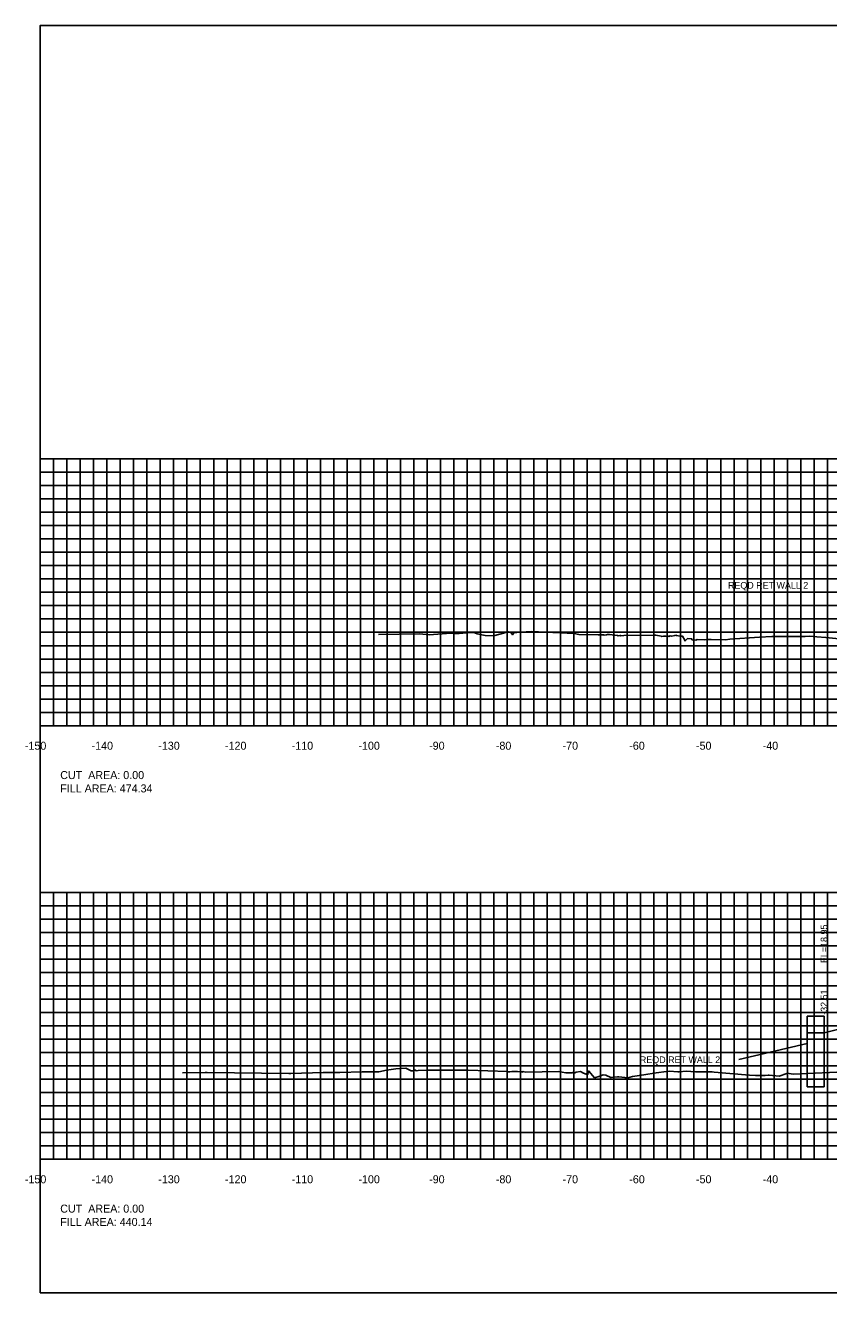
# Model space of a CAD drawing. Extents: x 1797518 to 1804843, y 248068 to 251132.
# Drawn here: x 1802478.8 to 1802599.2, y 250079.4 to 250269.4 of the extents above; entities that cross this region are included whole.
import ezdxf

# ---------------------------------------------------------------- set-up
doc = ezdxf.new("R2010")
doc.units = 0
for name, color, linetype in [('10', 7, 'Continuous'), ('3', 7, 'Continuous'), ('60', 7, 'Continuous'), ('ANNO-TXT', 7, 'Continuous'), ('CL-CNST', 7, 'Continuous'), ('Level 62', 7, 'Continuous'), ('M-ROADS', 7, 'Continuous')]:
    doc.layers.add(name, color=color, linetype=linetype)

msp = doc.modelspace()

# ---------------------------------------------------------------- linework, layer by layer
msp.add_line((1802598.49, 250118.38), (1802598.49, 250120.38))
msp.add_lwpolyline([(1802481, 250079.43), (1802781, 250079.43), (1802781, 250269.43), (1802481, 250269.43)], close=True)
at = {"layer": '3'}
msp.add_line((1802585.74, 250114.4), (1802595.99, 250116.8), dxfattribs=at)
at = {"layer": '60'}
for p, q in [((1802480.94, 250204.43), (1802481, 250204.43)), ((1802481, 250164.43), (1802481, 250204.43)), ((1802480.94, 250194.43), (1802481, 250194.43)), ((1802480.94, 250184.43), (1802481, 250184.43)), ((1802480.94, 250174.43), (1802481, 250174.43)), ((1802480.94, 250164.43), (1802481, 250164.43)), ((1802481, 250164.43), (1802781, 250164.43)), ((1802481, 250164.37), (1802481, 250164.43)), ((1802491, 250164.37), (1802491, 250164.43)), ((1802501, 250164.37), (1802501, 250164.43)), ((1802511, 250164.37), (1802511, 250164.43)), ((1802521, 250164.37), (1802521, 250164.43)), ((1802531, 250164.37), (1802531, 250164.43)), ((1802541, 250164.37), (1802541, 250164.43)), ((1802551, 250164.37), (1802551, 250164.43)), ((1802561, 250164.37), (1802561, 250164.43)), ((1802571, 250164.37), (1802571, 250164.43)), ((1802581, 250164.37), (1802581, 250164.43)), ((1802591, 250164.37), (1802591, 250164.43)), ((1802480.94, 250139.43), (1802481, 250139.43)), ((1802481, 250099.43), (1802481, 250139.43)), ((1802480.94, 250129.43), (1802481, 250129.43)), ((1802480.94, 250119.43), (1802481, 250119.43)), ((1802480.94, 250109.43), (1802481, 250109.43)), ((1802480.94, 250099.43), (1802481, 250099.43)), ((1802481, 250099.43), (1802781, 250099.43)), ((1802481, 250099.37), (1802481, 250099.43)), ((1802491, 250099.37), (1802491, 250099.43)), ((1802501, 250099.37), (1802501, 250099.43)), ((1802511, 250099.37), (1802511, 250099.43)), ((1802521, 250099.37), (1802521, 250099.43)), ((1802531, 250099.37), (1802531, 250099.43)), ((1802541, 250099.37), (1802541, 250099.43)), ((1802551, 250099.37), (1802551, 250099.43)), ((1802561, 250099.37), (1802561, 250099.43)), ((1802571, 250099.37), (1802571, 250099.43)), ((1802581, 250099.37), (1802581, 250099.43)), ((1802591, 250099.37), (1802591, 250099.43))]:
    msp.add_line(p, q, dxfattribs=at)
at = {"layer": 'CL-CNST'}
msp.add_lwpolyline([(1802598.49, 250118.38), (1802621, 250124.01), (1802623, 250124.09), (1802631, 250124.41), (1802655, 250125.28), (1802659, 250125.36), (1802661, 250125.38)], dxfattribs=at)
for points in [[(1802598.49, 250118.38), (1802595.99, 250118.38), (1802595.99, 250120.88), (1802598.49, 250120.88)], [(1802595.99, 250110.29), (1802598.49, 250110.29), (1802598.49, 250118.38), (1802595.99, 250118.38)]]:
    msp.add_lwpolyline(points, close=True, dxfattribs=at)
at = {"layer": 'Level 62'}
for p, q in [((1802481, 250204.43), (1802781, 250204.43)), ((1802481, 250164.43), (1802481, 250204.43)), ((1802483, 250164.43), (1802483, 250204.43)), ((1802485, 250164.43), (1802485, 250204.43)), ((1802487, 250164.43), (1802487, 250204.43)), ((1802489, 250164.43), (1802489, 250204.43)), ((1802491, 250164.43), (1802491, 250204.43)), ((1802493, 250164.43), (1802493, 250204.43)), ((1802495, 250164.43), (1802495, 250204.43)), ((1802497, 250164.43), (1802497, 250204.43)), ((1802499, 250164.43), (1802499, 250204.43)), ((1802501, 250164.43), (1802501, 250204.43)), ((1802503, 250164.43), (1802503, 250204.43)), ((1802505, 250164.43), (1802505, 250204.43)), ((1802507, 250164.43), (1802507, 250204.43)), ((1802509, 250164.43), (1802509, 250204.43)), ((1802511, 250164.43), (1802511, 250204.43)), ((1802513, 250164.43), (1802513, 250204.43)), ((1802515, 250164.43), (1802515, 250204.43)), ((1802517, 250164.43), (1802517, 250204.43)), ((1802519, 250164.43), (1802519, 250204.43)), ((1802521, 250164.43), (1802521, 250204.43)), ((1802523, 250164.43), (1802523, 250204.43)), ((1802525, 250164.43), (1802525, 250204.43)), ((1802527, 250164.43), (1802527, 250204.43)), ((1802529, 250164.43), (1802529, 250204.43)), ((1802531, 250164.43), (1802531, 250204.43)), ((1802533, 250164.43), (1802533, 250204.43)), ((1802535, 250164.43), (1802535, 250204.43)), ((1802537, 250164.43), (1802537, 250204.43)), ((1802539, 250164.43), (1802539, 250204.43)), ((1802541, 250164.43), (1802541, 250204.43)), ((1802543, 250164.43), (1802543, 250204.43)), ((1802545, 250164.43), (1802545, 250204.43)), ((1802547, 250164.43), (1802547, 250204.43)), ((1802549, 250164.43), (1802549, 250204.43)), ((1802551, 250164.43), (1802551, 250204.43)), ((1802553, 250164.43), (1802553, 250204.43)), ((1802555, 250164.43), (1802555, 250204.43)), ((1802557, 250164.43), (1802557, 250204.43)), ((1802559, 250164.43), (1802559, 250204.43)), ((1802561, 250164.43), (1802561, 250204.43)), ((1802563, 250164.43), (1802563, 250204.43)), ((1802565, 250164.43), (1802565, 250204.43)), ((1802567, 250164.43), (1802567, 250204.43)), ((1802569, 250164.43), (1802569, 250204.43)), ((1802571, 250164.43), (1802571, 250204.43)), ((1802573, 250164.43), (1802573, 250204.43)), ((1802575, 250164.43), (1802575, 250204.43)), ((1802577, 250164.43), (1802577, 250204.43)), ((1802579, 250164.43), (1802579, 250204.43)), ((1802581, 250164.43), (1802581, 250204.43)), ((1802583, 250164.43), (1802583, 250204.43)), ((1802585, 250164.43), (1802585, 250204.43)), ((1802587, 250164.43), (1802587, 250204.43)), ((1802589, 250164.43), (1802589, 250204.43)), ((1802591, 250164.43), (1802591, 250204.43)), ((1802593, 250164.43), (1802593, 250204.43)), ((1802595, 250164.43), (1802595, 250204.43)), ((1802597, 250164.43), (1802597, 250204.43)), ((1802599, 250164.43), (1802599, 250204.43)), ((1802481, 250202.43), (1802781, 250202.43)), ((1802481, 250200.43), (1802781, 250200.43)), ((1802481, 250198.43), (1802781, 250198.43)), ((1802481, 250196.43), (1802781, 250196.43)), ((1802481, 250194.43), (1802781, 250194.43)), ((1802481, 250192.43), (1802781, 250192.43)), ((1802481, 250190.43), (1802781, 250190.43)), ((1802481, 250188.43), (1802781, 250188.43)), ((1802481, 250186.43), (1802781, 250186.43)), ((1802481, 250184.43), (1802781, 250184.43)), ((1802481, 250182.43), (1802781, 250182.43)), ((1802481, 250180.43), (1802781, 250180.43)), ((1802481, 250178.43), (1802781, 250178.43)), ((1802481, 250176.43), (1802781, 250176.43)), ((1802481, 250174.43), (1802781, 250174.43)), ((1802481, 250172.43), (1802781, 250172.43)), ((1802481, 250170.43), (1802781, 250170.43)), ((1802481, 250168.43), (1802781, 250168.43)), ((1802481, 250166.43), (1802781, 250166.43)), ((1802481, 250164.43), (1802781, 250164.43)), ((1802481, 250139.43), (1802781, 250139.43)), ((1802481, 250099.43), (1802481, 250139.43)), ((1802483, 250099.43), (1802483, 250139.43)), ((1802485, 250099.43), (1802485, 250139.43)), ((1802487, 250099.43), (1802487, 250139.43)), ((1802489, 250099.43), (1802489, 250139.43)), ((1802491, 250099.43), (1802491, 250139.43)), ((1802493, 250099.43), (1802493, 250139.43)), ((1802495, 250099.43), (1802495, 250139.43)), ((1802497, 250099.43), (1802497, 250139.43)), ((1802499, 250099.43), (1802499, 250139.43)), ((1802501, 250099.43), (1802501, 250139.43)), ((1802503, 250099.43), (1802503, 250139.43)), ((1802505, 250099.43), (1802505, 250139.43)), ((1802507, 250099.43), (1802507, 250139.43)), ((1802509, 250099.43), (1802509, 250139.43)), ((1802511, 250099.43), (1802511, 250139.43)), ((1802513, 250099.43), (1802513, 250139.43)), ((1802515, 250099.43), (1802515, 250139.43)), ((1802517, 250099.43), (1802517, 250139.43)), ((1802519, 250099.43), (1802519, 250139.43)), ((1802521, 250099.43), (1802521, 250139.43)), ((1802523, 250099.43), (1802523, 250139.43)), ((1802525, 250099.43), (1802525, 250139.43)), ((1802527, 250099.43), (1802527, 250139.43)), ((1802529, 250099.43), (1802529, 250139.43)), ((1802531, 250099.43), (1802531, 250139.43)), ((1802533, 250099.43), (1802533, 250139.43)), ((1802535, 250099.43), (1802535, 250139.43)), ((1802537, 250099.43), (1802537, 250139.43)), ((1802539, 250099.43), (1802539, 250139.43)), ((1802541, 250099.43), (1802541, 250139.43)), ((1802543, 250099.43), (1802543, 250139.43)), ((1802545, 250099.43), (1802545, 250139.43)), ((1802547, 250099.43), (1802547, 250139.43)), ((1802549, 250099.43), (1802549, 250139.43)), ((1802551, 250099.43), (1802551, 250139.43)), ((1802553, 250099.43), (1802553, 250139.43)), ((1802555, 250099.43), (1802555, 250139.43)), ((1802557, 250099.43), (1802557, 250139.43)), ((1802559, 250099.43), (1802559, 250139.43)), ((1802561, 250099.43), (1802561, 250139.43)), ((1802563, 250099.43), (1802563, 250139.43)), ((1802565, 250099.43), (1802565, 250139.43)), ((1802567, 250099.43), (1802567, 250139.43)), ((1802569, 250099.43), (1802569, 250139.43)), ((1802571, 250099.43), (1802571, 250139.43)), ((1802573, 250099.43), (1802573, 250139.43)), ((1802575, 250099.43), (1802575, 250139.43)), ((1802577, 250099.43), (1802577, 250139.43)), ((1802579, 250099.43), (1802579, 250139.43)), ((1802581, 250099.43), (1802581, 250139.43)), ((1802583, 250099.43), (1802583, 250139.43)), ((1802585, 250099.43), (1802585, 250139.43)), ((1802587, 250099.43), (1802587, 250139.43)), ((1802589, 250099.43), (1802589, 250139.43)), ((1802591, 250099.43), (1802591, 250139.43)), ((1802593, 250099.43), (1802593, 250139.43)), ((1802595, 250099.43), (1802595, 250139.43)), ((1802597, 250099.43), (1802597, 250139.43)), ((1802599, 250099.43), (1802599, 250139.43)), ((1802481, 250137.43), (1802781, 250137.43)), ((1802481, 250135.43), (1802781, 250135.43)), ((1802481, 250133.43), (1802781, 250133.43)), ((1802481, 250131.43), (1802781, 250131.43)), ((1802481, 250129.43), (1802781, 250129.43)), ((1802481, 250127.43), (1802781, 250127.43)), ((1802481, 250125.43), (1802781, 250125.43)), ((1802481, 250123.43), (1802781, 250123.43)), ((1802481, 250121.43), (1802781, 250121.43)), ((1802481, 250119.43), (1802781, 250119.43)), ((1802481, 250117.43), (1802781, 250117.43)), ((1802481, 250115.43), (1802781, 250115.43)), ((1802481, 250113.43), (1802781, 250113.43)), ((1802481, 250111.43), (1802781, 250111.43)), ((1802481, 250109.43), (1802781, 250109.43)), ((1802481, 250107.43), (1802781, 250107.43)), ((1802481, 250105.43), (1802781, 250105.43)), ((1802481, 250103.43), (1802781, 250103.43)), ((1802481, 250101.43), (1802781, 250101.43)), ((1802481, 250099.43), (1802781, 250099.43))]:
    msp.add_line(p, q, dxfattribs=at)
at = {"layer": 'M-ROADS'}
for points in [[(1802531.72, 250178.09), (1802537.88, 250178.21), (1802539.29, 250178.07), (1802542.54, 250178.3), (1802542.92, 250178.27), (1802543.78, 250178.28), (1802545.38, 250178.38), (1802545.99, 250178.38), (1802546.52, 250178.19), (1802547.68, 250177.97), (1802548.95, 250177.89), (1802550.66, 250178.35), (1802550.79, 250178.43), (1802550.81, 250178.43), (1802550.82, 250178.43), (1802551.17, 250178.52), (1802551.35, 250178.45), (1802551.57, 250178.39), (1802551.72, 250178.16), (1802551.81, 250178.08), (1802552, 250178.35), (1802552.9, 250178.47), (1802553.82, 250178.52), (1802554.62, 250178.54), (1802561.06, 250178.28), (1802561.75, 250178.11), (1802564.65, 250178.08), (1802564.67, 250178.08), (1802565.43, 250178.05), (1802565.52, 250178.03), (1802565.88, 250178.04), (1802566.05, 250178.1), (1802566.33, 250178.1), (1802566.74, 250178.08), (1802567.51, 250177.97), (1802567.65, 250177.91), (1802567.91, 250177.96), (1802568.01, 250177.94), (1802568.02, 250177.9), (1802568.49, 250177.95), (1802573.14, 250177.99), (1802573.2, 250177.99), (1802573.26, 250177.99), (1802574.06, 250177.85), (1802574.11, 250177.83), (1802574.17, 250177.81), (1802574.46, 250177.86), (1802574.73, 250177.87), (1802574.78, 250177.88), (1802574.98, 250177.81), (1802574.99, 250177.84), (1802575.15, 250177.85), (1802575.19, 250177.84), (1802575.25, 250177.8), (1802575.45, 250177.89), (1802575.64, 250177.87), (1802575.7, 250177.87), (1802576.12, 250177.95), (1802576.27, 250177.99), (1802576.38, 250177.98), (1802576.94, 250177.87), (1802577.04, 250177.79), (1802577.04, 250177.83), (1802577.05, 250177.87), (1802577.08, 250177.86), (1802577.28, 250177.84), (1802577.61, 250177.27), (1802577.64, 250177.15), (1802577.67, 250177.18), (1802578.03, 250177.52), (1802578.63, 250177.48), (1802578.71, 250177.33), (1802579.26, 250177.28), (1802579.48, 250177.36), (1802580.55, 250177.32), (1802581.08, 250177.36), (1802581.57, 250177.35), (1802581.58, 250177.35), (1802581.6, 250177.35), (1802583.71, 250177.33), (1802584.37, 250177.42), (1802588.84, 250177.71), (1802590.69, 250177.8), (1802591.9, 250177.8), (1802592.99, 250177.8), (1802593.32, 250177.8), (1802593.48, 250177.8), (1802594, 250177.8), (1802595.69, 250177.8), (1802596.3, 250177.84), (1802597.43, 250177.77), (1802598.77, 250177.64), (1802601.27, 250177.4)], [(1802502.33, 250112.39), (1802505.71, 250112.45), (1802506, 250112.45), (1802518.29, 250112.27), (1802518.55, 250112.27), (1802523.42, 250112.42), (1802524.91, 250112.43), (1802525.33, 250112.43), (1802525.74, 250112.43), (1802525.91, 250112.46), (1802529.27, 250112.55), (1802531.76, 250112.54), (1802532.9, 250112.78), (1802534.33, 250112.97), (1802535.81, 250113.08), (1802536.59, 250112.67), (1802536.73, 250112.68), (1802536.86, 250112.68), (1802536.93, 250112.7), (1802536.97, 250112.69), (1802537.14, 250112.82), (1802537.37, 250112.68), (1802537.67, 250112.72), (1802538.99, 250112.8), (1802539.56, 250112.8), (1802539.95, 250112.79), (1802542.08, 250112.81), (1802542.52, 250112.81), (1802545.14, 250112.78), (1802551.03, 250112.59), (1802551.21, 250112.52), (1802551.41, 250112.55), (1802551.71, 250112.6), (1802552.19, 250112.59), (1802552.55, 250112.58), (1802553.2, 250112.52), (1802553.31, 250112.5), (1802553.36, 250112.59), (1802553.81, 250112.49), (1802558.68, 250112.6), (1802559.8, 250112.39), (1802560.5, 250112.4), (1802560.73, 250112.39), (1802560.76, 250112.37), (1802560.83, 250112.42), (1802560.98, 250112.59), (1802561.06, 250112.37), (1802561.06, 250112.34), (1802561.33, 250112.49), (1802562.01, 250112.6), (1802562.43, 250112.32), (1802562.61, 250112.27), (1802562.69, 250112.23), (1802562.77, 250112.2), (1802563.04, 250112.35), (1802563.1, 250112.37), (1802563.1, 250112.17), (1802563.12, 250112.43), (1802563.21, 250112.66), (1802563.21, 250112.65), (1802563.22, 250112.66), (1802563.22, 250112.66), (1802563.24, 250112.65), (1802564.09, 250111.65), (1802564.76, 250111.85), (1802565.4, 250112.11), (1802565.78, 250112.06), (1802566.55, 250111.67), (1802566.59, 250111.67), (1802567.51, 250111.78), (1802567.58, 250111.81), (1802567.71, 250111.78), (1802569.09, 250111.65), (1802569.76, 250111.85), (1802571.47, 250112.11), (1802573.32, 250112.37), (1802574.87, 250112.61), (1802575.35, 250112.62), (1802576.59, 250112.55), (1802576.77, 250112.55), (1802577.85, 250112.63), (1802578.52, 250112.61), (1802579.22, 250112.54), (1802579.27, 250112.56), (1802579.29, 250112.54), (1802581.4, 250112.54), (1802581.57, 250112.55), (1802581.73, 250112.54), (1802582.05, 250112.51), (1802587.31, 250112.02), (1802588.2, 250112.01), (1802589.67, 250112.01), (1802590.1, 250112.03), (1802590.14, 250112.03), (1802590.28, 250112.03), (1802591.76, 250111.88), (1802592.9, 250112.3), (1802592.97, 250112.33), (1802593.87, 250112.2), (1802602.63, 250112.6)]]:
    msp.add_lwpolyline(points, dxfattribs=at)

# ---------------------------------------------------------------- texts
at = {"layer": '10'}
for s, p in [('-150', (1802478.7, 250160.83)), ('-140', (1802488.7, 250160.83)), ('-130', (1802498.7, 250160.83)), ('-120', (1802508.7, 250160.83)), ('-110', (1802518.7, 250160.83)), ('-100', (1802528.7, 250160.83)), ('-90', (1802539.3, 250160.83)), ('-80', (1802549.3, 250160.83)), ('-70', (1802559.3, 250160.83)), ('-60', (1802569.3, 250160.83)), ('-50', (1802579.3, 250160.83)), ('-40', (1802589.3, 250160.83)), ('-150', (1802478.7, 250095.83)), ('-140', (1802488.7, 250095.83)), ('-130', (1802498.7, 250095.83)), ('-120', (1802508.7, 250095.83)), ('-110', (1802518.7, 250095.83)), ('-100', (1802528.7, 250095.83)), ('-90', (1802539.3, 250095.83)), ('-80', (1802549.3, 250095.83)), ('-70', (1802559.3, 250095.83)), ('-60', (1802569.3, 250095.83)), ('-50', (1802579.3, 250095.83)), ('-40', (1802589.3, 250095.83))]:
    msp.add_text(s, height=1.2, dxfattribs=at).set_placement(p)
at = {"layer": '3'}
for p in [(1802584.09, 250184.98), (1802570.89, 250113.85)]:
    msp.add_text('REQD RET WALL 2', height=1, dxfattribs=at).set_placement(p)
for s, p in [('EL=18.95', (1802598.99, 250128.85)), ('-32.51', (1802598.99, 250121.09))]:
    msp.add_text(s, height=1, rotation=90, dxfattribs=at).set_placement(p)
at = {"layer": '60'}
for p in [(1802481, 250164.43), (1802481, 250099.43)]:
    msp.add_text('-', height=0.0001, dxfattribs=at).set_placement(p)
at = {"layer": 'ANNO-TXT'}
for s, p in [('CUT  AREA: 0.00', (1802484, 250156.43)), ('FILL AREA: 474.34', (1802484, 250154.43)), ('CUT  AREA: 0.00', (1802484, 250091.43)), ('FILL AREA: 440.14', (1802484, 250089.43))]:
    msp.add_text(s, height=1.2, dxfattribs=at).set_placement(p)

doc.saveas('drawing.dxf')
